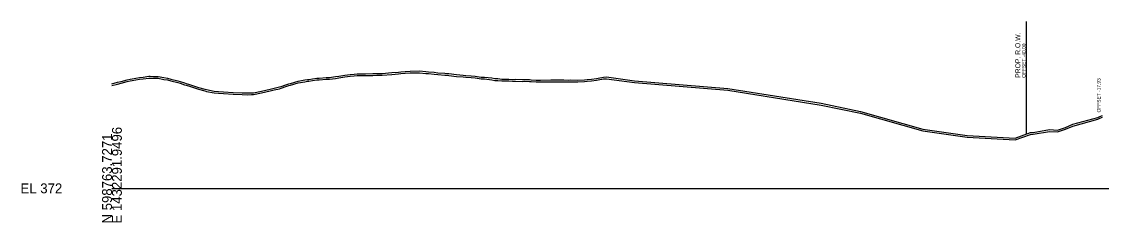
# Model space of a CAD drawing. Extents: x -26 to 2203, y -10 to 12201.
# Drawn here: x -25.7 to 281.3, y 9490.3 to 9547.5 of the extents above; entities that cross this region are included whole.
import ezdxf

# ---------------------------------------------------------------- set-up
doc = ezdxf.new("R2010")
doc.units = 0
for name, color, linetype in [('DESIGN - ROW - Right-of-Way and Easement Labels', 7, 'Continuous'), ('DESIGN - ROW - Right-of-Way Linework', 7, 'Continuous'), ('DESIGN - SHEET - Light Grid', 7, 'Continuous'), ('DESIGN - TYPICAL - Slope Tie Text', 7, 'Continuous'), ('SURVEY - GROUND - Bottom of Topsoil Layer', 7, 'Continuous'), ('SURVEY - GROUND - Top of Ground', 7, 'Continuous')]:
    doc.layers.add(name, color=color, linetype=linetype)

msp = doc.modelspace()

# ---------------------------------------------------------------- linework, layer by layer
at = {"layer": 'DESIGN - ROW - Right-of-Way Linework'}
msp.add_line((260, 9515.45), (260, 9547.45), dxfattribs=at)
at = {"layer": 'DESIGN - SHEET - Light Grid'}
msp.add_line((0, 9500), (300, 9500), dxfattribs=at)
at = {"layer": 'SURVEY - GROUND - Bottom of Topsoil Layer'}
for p, q in [((79.58, 9532.44), (81.43, 9532.58)), ((81.43, 9532.58), (82.09, 9532.68)), ((82.09, 9532.68), (83.39, 9532.74)), ((83.39, 9532.74), (84.74, 9532.84)), ((84.74, 9532.84), (87.39, 9532.91)), ((87.39, 9532.91), (89.28, 9532.72)), ((89.28, 9532.72), (90.04, 9532.65)), ((90.04, 9532.65), (91.63, 9532.53)), ((91.63, 9532.53), (92.69, 9532.38)), ((0, 9529.26), (1.62, 9529.67)), ((1.62, 9529.67), (2.57, 9529.95)), ((2.57, 9529.95), (4.31, 9530.37)), ((4.31, 9530.37), (5.22, 9530.59)), ((5.22, 9530.59), (5.71, 9530.69)), ((5.71, 9530.69), (7.87, 9531.04)), ((7.87, 9531.04), (8.9, 9531.15)), ((8.9, 9531.15), (10.52, 9531.39)), ((10.52, 9531.39), (10.86, 9531.39)), ((10.86, 9531.39), (11.84, 9531.36)), ((11.84, 9531.36), (12.82, 9531.32)), ((12.82, 9531.32), (13.17, 9531.33)), ((13.17, 9531.33), (14.78, 9531)), ((14.78, 9531), (15.82, 9530.87)), ((15.82, 9530.87), (16.74, 9530.55)), ((16.74, 9530.55), (18.7, 9530.09)), ((18.7, 9530.09), (19.37, 9529.9)), ((19.37, 9529.9), (20.67, 9529.5)), ((20.67, 9529.5), (21.12, 9529.37)), ((50.72, 9529.34), (52.93, 9529.99)), ((52.93, 9529.99), (54.81, 9530.34)), ((54.81, 9530.34), (55.58, 9530.48)), ((55.58, 9530.48), (55.95, 9530.51)), ((55.95, 9530.51), (57, 9530.67)), ((57, 9530.67), (58.23, 9530.83)), ((58.23, 9530.83), (58.9, 9530.88)), ((58.9, 9530.88), (60.88, 9531.02)), ((60.88, 9531.02), (61.83, 9531.05)), ((61.83, 9531.05), (63.53, 9531.3)), ((63.53, 9531.3), (64.53, 9531.45)), ((64.53, 9531.45), (66.18, 9531.75)), ((66.18, 9531.75), (67.71, 9531.93)), ((67.71, 9531.93), (68.83, 9532.03)), ((68.83, 9532.03), (69.67, 9532.07)), ((69.67, 9532.07), (71.49, 9532.09)), ((71.49, 9532.09), (72.05, 9532.1)), ((72.05, 9532.1), (74.14, 9532.14)), ((74.14, 9532.14), (75.27, 9532.18)), ((75.27, 9532.18), (76.79, 9532.2)), ((76.79, 9532.2), (79.58, 9532.44)), ((92.69, 9532.38), (94.63, 9532.25)), ((94.63, 9532.25), (95.34, 9532.2)), ((95.34, 9532.2), (95.73, 9532.14)), ((95.73, 9532.14), (97.99, 9531.87)), ((97.99, 9531.87), (99.82, 9531.7)), ((99.82, 9531.7), (100.64, 9531.64)), ((100.64, 9531.64), (102.16, 9531.56)), ((102.16, 9531.56), (103.29, 9531.46)), ((103.29, 9531.46), (104.96, 9531.17)), ((104.96, 9531.17), (105.94, 9531.15)), ((105.94, 9531.15), (108, 9530.92)), ((108, 9530.92), (108.88, 9530.72)), ((108.88, 9530.72), (109.69, 9530.71)), ((109.69, 9530.71), (110.84, 9530.6)), ((110.84, 9530.6), (111.24, 9530.59)), ((111.24, 9530.59), (112.8, 9530.55)), ((112.8, 9530.55), (113.9, 9530.5)), ((113.9, 9530.5), (114.76, 9530.52)), ((114.76, 9530.52), (116.72, 9530.45)), ((116.72, 9530.45), (117.21, 9530.47)), ((117.21, 9530.47), (118.68, 9530.44)), ((118.68, 9530.44), (119.2, 9530.42)), ((119.2, 9530.42), (120.64, 9530.29)), ((120.64, 9530.29), (121.85, 9530.29)), ((121.85, 9530.29), (124.74, 9530.35)), ((124.74, 9530.35), (126.52, 9530.34)), ((126.52, 9530.34), (127.15, 9530.35)), ((127.15, 9530.35), (128.46, 9530.34)), ((128.46, 9530.34), (129.8, 9530.32)), ((129.8, 9530.32), (130.44, 9530.34)), ((130.44, 9530.34), (132.45, 9530.31)), ((132.45, 9530.31), (134.36, 9530.42)), ((134.36, 9530.42), (135.1, 9530.47)), ((135.1, 9530.47), (136.32, 9530.6)), ((136.32, 9530.6), (137.75, 9530.8)), ((137.75, 9530.8), (138.28, 9530.88)), ((138.28, 9530.88), (139.79, 9531.15)), ((139.79, 9531.15), (140.59, 9531.2)), ((140.59, 9531.2), (148.61, 9530.1)), ((148.61, 9530.1), (175.08, 9527.93)), ((21.12, 9529.37), (22.08, 9529.05)), ((22.08, 9529.05), (23.77, 9528.47)), ((23.77, 9528.47), (24.59, 9528.2)), ((24.59, 9528.2), (26.42, 9527.71)), ((26.42, 9527.71), (26.89, 9527.6)), ((26.89, 9527.6), (29.07, 9527.2)), ((29.07, 9527.2), (30.26, 9527.08)), ((30.26, 9527.08), (31.73, 9526.99)), ((31.73, 9526.99), (34.42, 9526.82)), ((34.42, 9526.82), (37.03, 9526.67)), ((37.03, 9526.67), (38.44, 9526.65)), ((38.44, 9526.65), (39.68, 9526.66)), ((39.68, 9526.66), (40.27, 9526.72)), ((40.27, 9526.72), (42.54, 9527.15)), ((42.54, 9527.15), (44.98, 9527.73)), ((44.98, 9527.73), (46.15, 9528)), ((46.15, 9528), (47.63, 9528.36)), ((47.63, 9528.36), (48.11, 9528.48)), ((48.11, 9528.48), (49.47, 9528.96)), ((49.47, 9528.96), (50.28, 9529.22)), ((50.28, 9529.22), (50.72, 9529.34)), ((175.08, 9527.93), (201.62, 9523.71)), ((201.62, 9523.71), (212.78, 9521.38)), ((212.78, 9521.38), (230.53, 9516.32)), ((271.06, 9516.82), (273.2, 9517.73)), ((273.2, 9517.73), (280.32, 9519.65)), ((280.32, 9519.65), (280.91, 9519.99)), ((280.91, 9519.99), (281.62, 9520.21)), ((230.53, 9516.32), (243.11, 9514.57)), ((243.11, 9514.57), (256.79, 9513.77)), ((256.79, 9513.77), (261.11, 9515.36)), ((261.11, 9515.36), (261.87, 9515.4)), ((261.87, 9515.4), (266.53, 9516.21)), ((266.53, 9516.21), (268.83, 9516.05)), ((268.83, 9516.05), (271.06, 9516.82))]:
    msp.add_line(p, q, dxfattribs=at)
at = {"layer": 'SURVEY - GROUND - Top of Ground'}
for p, q in [((67.71, 9532.43), (68.83, 9532.53)), ((68.83, 9532.53), (69.67, 9532.57)), ((69.67, 9532.57), (71.49, 9532.59)), ((71.49, 9532.59), (72.05, 9532.6)), ((72.05, 9532.6), (74.14, 9532.64)), ((74.14, 9532.64), (75.27, 9532.68)), ((75.27, 9532.68), (76.79, 9532.7)), ((76.79, 9532.7), (79.58, 9532.94)), ((79.58, 9532.94), (81.43, 9533.08)), ((81.43, 9533.08), (82.09, 9533.18)), ((82.09, 9533.18), (83.39, 9533.24)), ((83.39, 9533.24), (84.74, 9533.34)), ((84.74, 9533.34), (87.39, 9533.41)), ((87.39, 9533.41), (89.28, 9533.22)), ((89.28, 9533.22), (90.04, 9533.15)), ((90.04, 9533.15), (91.63, 9533.03)), ((91.63, 9533.03), (92.69, 9532.88)), ((92.69, 9532.88), (94.63, 9532.75)), ((94.63, 9532.75), (95.34, 9532.7)), ((95.34, 9532.7), (95.73, 9532.64)), ((95.73, 9532.64), (97.99, 9532.37)), ((0, 9529.76), (1.62, 9530.17)), ((1.62, 9530.17), (2.57, 9530.45)), ((2.57, 9530.45), (4.31, 9530.87)), ((4.31, 9530.87), (5.22, 9531.09)), ((5.22, 9531.09), (5.71, 9531.19)), ((5.71, 9531.19), (7.87, 9531.54)), ((7.87, 9531.54), (8.9, 9531.65)), ((8.9, 9531.65), (10.52, 9531.89)), ((10.52, 9531.89), (10.86, 9531.89)), ((10.86, 9531.89), (11.84, 9531.86)), ((11.84, 9531.86), (12.82, 9531.82)), ((12.82, 9531.82), (13.17, 9531.83)), ((13.17, 9531.83), (14.78, 9531.5)), ((14.78, 9531.5), (15.82, 9531.37)), ((15.82, 9531.37), (16.74, 9531.05)), ((16.74, 9531.05), (18.7, 9530.59)), ((18.7, 9530.59), (19.37, 9530.4)), ((19.37, 9530.4), (20.67, 9530)), ((20.67, 9530), (21.12, 9529.87)), ((21.12, 9529.87), (22.08, 9529.55)), ((22.08, 9529.55), (23.77, 9528.97)), ((48.11, 9528.98), (49.47, 9529.46)), ((49.47, 9529.46), (50.28, 9529.72)), ((50.28, 9529.72), (50.72, 9529.84)), ((50.72, 9529.84), (52.93, 9530.49)), ((52.93, 9530.49), (54.81, 9530.84)), ((54.81, 9530.84), (55.58, 9530.98)), ((55.58, 9530.98), (55.95, 9531.01)), ((55.95, 9531.01), (57, 9531.17)), ((57, 9531.17), (58.23, 9531.33)), ((58.23, 9531.33), (58.9, 9531.38)), ((58.9, 9531.38), (60.88, 9531.52)), ((60.88, 9531.52), (61.83, 9531.55)), ((61.83, 9531.55), (63.53, 9531.8)), ((63.53, 9531.8), (64.53, 9531.95)), ((64.53, 9531.95), (66.18, 9532.25)), ((66.18, 9532.25), (67.71, 9532.43)), ((97.99, 9532.37), (99.82, 9532.2)), ((99.82, 9532.2), (100.64, 9532.14)), ((100.64, 9532.14), (102.16, 9532.06)), ((102.16, 9532.06), (103.29, 9531.96)), ((103.29, 9531.96), (104.96, 9531.67)), ((104.96, 9531.67), (105.94, 9531.65)), ((105.94, 9531.65), (108, 9531.42)), ((108, 9531.42), (108.88, 9531.22)), ((108.88, 9531.22), (109.69, 9531.21)), ((109.69, 9531.21), (110.84, 9531.1)), ((110.84, 9531.1), (111.24, 9531.09)), ((111.24, 9531.09), (112.8, 9531.05)), ((112.8, 9531.05), (113.9, 9531)), ((113.9, 9531), (114.76, 9531.02)), ((114.76, 9531.02), (116.72, 9530.95)), ((116.72, 9530.95), (117.21, 9530.97)), ((117.21, 9530.97), (118.68, 9530.94)), ((118.68, 9530.94), (119.2, 9530.92)), ((119.2, 9530.92), (120.64, 9530.79)), ((120.64, 9530.79), (121.85, 9530.79)), ((121.85, 9530.79), (124.74, 9530.85)), ((124.74, 9530.85), (126.52, 9530.84)), ((126.52, 9530.84), (127.15, 9530.85)), ((127.15, 9530.85), (128.46, 9530.84)), ((128.46, 9530.84), (129.8, 9530.82)), ((129.8, 9530.82), (130.44, 9530.84)), ((130.44, 9530.84), (132.45, 9530.81)), ((132.45, 9530.81), (134.36, 9530.92)), ((134.36, 9530.92), (135.1, 9530.97)), ((135.1, 9530.97), (136.32, 9531.1)), ((136.32, 9531.1), (137.75, 9531.3)), ((137.75, 9531.3), (138.28, 9531.38)), ((138.28, 9531.38), (139.79, 9531.65)), ((139.79, 9531.65), (140.59, 9531.7)), ((140.59, 9531.7), (148.61, 9530.6)), ((148.61, 9530.6), (175.08, 9528.43)), ((23.77, 9528.97), (24.59, 9528.7)), ((24.59, 9528.7), (26.42, 9528.21)), ((26.42, 9528.21), (26.89, 9528.1)), ((26.89, 9528.1), (29.07, 9527.7)), ((29.07, 9527.7), (30.26, 9527.58)), ((30.26, 9527.58), (31.73, 9527.49)), ((31.73, 9527.49), (34.42, 9527.32)), ((34.42, 9527.32), (37.03, 9527.17)), ((37.03, 9527.17), (38.44, 9527.15)), ((38.44, 9527.15), (39.68, 9527.16)), ((39.68, 9527.16), (40.27, 9527.22)), ((40.27, 9527.22), (42.54, 9527.65)), ((42.54, 9527.65), (44.98, 9528.23)), ((44.98, 9528.23), (46.15, 9528.5)), ((46.15, 9528.5), (47.63, 9528.86)), ((47.63, 9528.86), (48.11, 9528.98)), ((175.08, 9528.43), (201.62, 9524.21)), ((201.62, 9524.21), (212.78, 9521.88)), ((212.78, 9521.88), (230.53, 9516.82)), ((280.32, 9520.15), (280.91, 9520.49)), ((280.91, 9520.49), (281.62, 9520.71)), ((268.83, 9516.55), (271.06, 9517.32)), ((271.06, 9517.32), (273.2, 9518.23)), ((273.2, 9518.23), (280.32, 9520.15)), ((230.53, 9516.82), (243.11, 9515.07)), ((243.11, 9515.07), (256.79, 9514.27)), ((256.79, 9514.27), (261.11, 9515.86)), ((261.11, 9515.86), (261.87, 9515.9)), ((261.87, 9515.9), (266.53, 9516.71)), ((266.53, 9516.71), (268.83, 9516.55))]:
    msp.add_line(p, q, dxfattribs=at)

# ---------------------------------------------------------------- texts
at = {"layer": 'DESIGN - ROW - Right-of-Way and Easement Labels'}
for s, height, p in [('PROP. R.O.W.', 1.4, (258.25, 9531.45)), ('OFFSET -40.00', 1, (259.75, 9531.45))]:
    msp.add_text(s, height=height, rotation=90, dxfattribs=at).set_placement(p)
at = {"layer": 'DESIGN - SHEET - Light Grid'}
for s, p in [('E 1432291.9496', (2.8, 9490)), ('N 598763.7271', (0, 9490))]:
    msp.add_text(s, height=2.8, rotation=90, dxfattribs=at).set_placement(p)
msp.add_text('EL 372', height=2.8, dxfattribs=at).set_placement((-26, 9498.6))
at = {"layer": 'DESIGN - TYPICAL - Slope Tie Text'}
msp.add_text('OFFSET -17.93', height=1, rotation=90, dxfattribs=at).set_placement((281.07, 9521.59))

doc.saveas('drawing.dxf')
